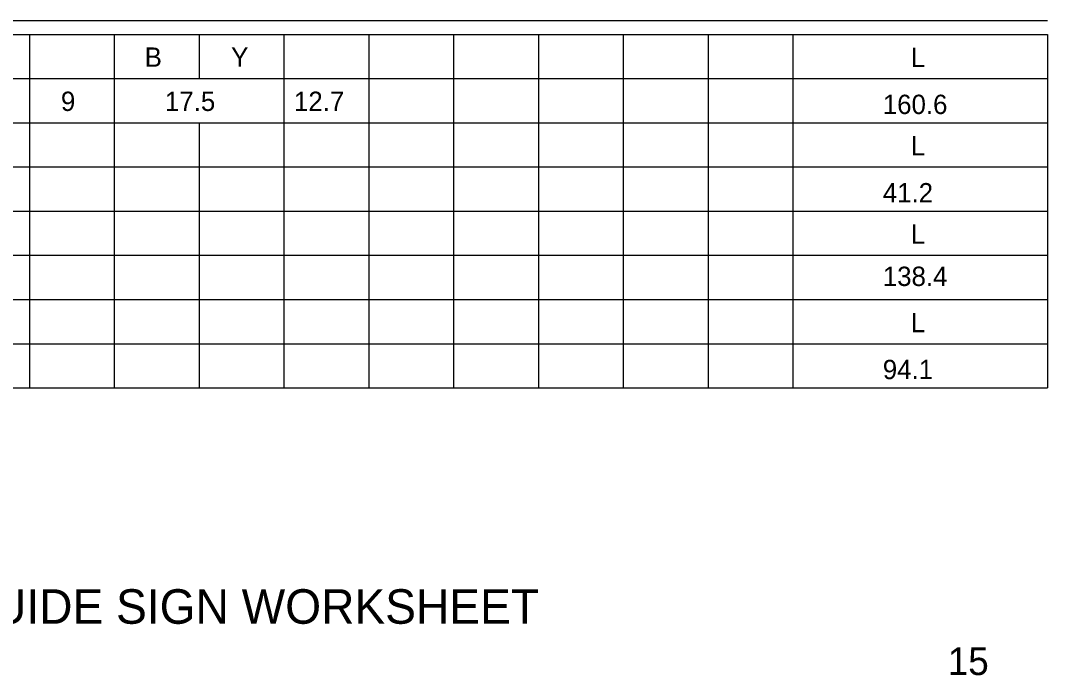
# Model space of a CAD drawing. Extents: x 10268312 to 10268472, y 2142583 to 2142688.
# Drawn here: x 10268433.77 to 10268470.98, y 2142585.82 to 2142609.53 of the extents above; entities that cross this region are included whole.
import ezdxf

# ---------------------------------------------------------------- set-up
doc = ezdxf.new("R2010")
doc.units = 0
for name, color, linetype in [('SumBoxLines_dp', 7, 'Continuous'), ('SumBoxLinesMin_dp', 7, 'Continuous'), ('TextLabel', 7, 'Continuous'), ('TextMisc', 7, 'Continuous'), ('TextShtNo', 7, 'Continuous')]:
    doc.layers.add(name, color=color, linetype=linetype)

msp = doc.modelspace()

# ---------------------------------------------------------------- linework, layer by layer
at = {"layer": 'SumBoxLines_dp'}
for p, q in [((10268418.73, 2142609.532), (10268470.98, 2142609.532)), ((10268395.48, 2142609.032), (10268470.98, 2142609.032)), ((10268395.48, 2142609.032), (10268470.98, 2142609.032)), ((10268434.098, 2142609.032), (10268434.098, 2142604.232)), ((10268434.098, 2142609.032), (10268434.098, 2142596.232)), ((10268437.171, 2142609.032), (10268437.171, 2142597.832)), ((10268437.171, 2142609.032), (10268437.171, 2142597.832)), ((10268437.171, 2142609.032), (10268437.171, 2142596.232)), ((10268440.245, 2142609.032), (10268440.245, 2142607.432)), ((10268443.318, 2142609.032), (10268443.318, 2142605.832)), ((10268446.392, 2142609.032), (10268446.392, 2142602.632)), ((10268449.465, 2142609.032), (10268449.465, 2142602.632)), ((10268452.539, 2142609.032), (10268452.539, 2142596.232)), ((10268452.539, 2142609.032), (10268452.539, 2142596.232)), ((10268455.612, 2142609.032), (10268455.612, 2142596.232)), ((10268455.612, 2142609.032), (10268455.612, 2142596.232)), ((10268458.686, 2142609.032), (10268458.686, 2142596.232)), ((10268461.759, 2142609.032), (10268461.759, 2142596.232)), ((10268470.98, 2142609.032), (10268470.98, 2142596.232)), ((10268395.48, 2142605.832), (10268470.98, 2142605.832)), ((10268440.245, 2142605.832), (10268440.245, 2142597.832)), ((10268440.245, 2142605.832), (10268440.245, 2142596.232)), ((10268443.318, 2142605.832), (10268443.318, 2142596.232)), ((10268446.392, 2142605.832), (10268446.392, 2142596.232)), ((10268449.465, 2142605.832), (10268449.465, 2142596.232)), ((10268458.686, 2142605.832), (10268458.686, 2142596.232)), ((10268461.759, 2142605.832), (10268461.759, 2142596.232)), ((10268461.759, 2142605.832), (10268461.759, 2142596.232)), ((10268470.98, 2142605.832), (10268470.98, 2142596.232)), ((10268395.48, 2142602.632), (10268470.98, 2142602.632)), ((10268434.098, 2142602.632), (10268434.098, 2142597.832)), ((10268395.48, 2142599.432), (10268470.98, 2142599.432)), ((10268395.48, 2142596.232), (10268470.98, 2142596.232))]:
    msp.add_line(p, q, dxfattribs=at)
at = {"layer": 'SumBoxLinesMin_dp'}
for p, q in [((10268395.48, 2142607.432), (10268470.98, 2142607.432)), ((10268395.48, 2142604.232), (10268470.98, 2142604.232)), ((10268395.48, 2142601.032), (10268470.98, 2142601.032)), ((10268395.48, 2142597.832), (10268470.98, 2142597.832))]:
    msp.add_line(p, q, dxfattribs=at)

# ---------------------------------------------------------------- texts
at = {"layer": 'TextLabel'}
for s, p in [('B', (10268438.272, 2142607.858)), ('Y', (10268441.405, 2142607.858)), ('L', (10268466.029, 2142607.848)), ('9', (10268435.238, 2142606.258)), ('17.5', (10268439.007, 2142606.258)), ('12.7', (10268443.682, 2142606.258)), ('L', (10268466.029, 2142604.648)), ('L', (10268466.029, 2142601.448)), ('L', (10268466.029, 2142598.248))]:
    msp.add_text(s, height=0.7, dxfattribs=at).set_placement(p)
at = {"layer": 'TextMisc'}
for s, p in [('160.6', (10268465.014, 2142606.147)), ('41.2', (10268465.014, 2142602.947)), ('138.4', (10268465.014, 2142599.921)), ('94.1', (10268465.014, 2142596.547))]:
    msp.add_text(s, height=0.7, dxfattribs=at).set_placement(p)
msp.add_text('     GUIDE SIGN WORKSHEET      ', height=1.25, rotation=360, dxfattribs=at).set_placement((10268429.155, 2142587.69))
at = {"layer": 'TextShtNo'}
msp.add_text('15', height=1, rotation=360, dxfattribs=at).set_placement((10268467.366, 2142585.833))

doc.saveas('drawing.dxf')
